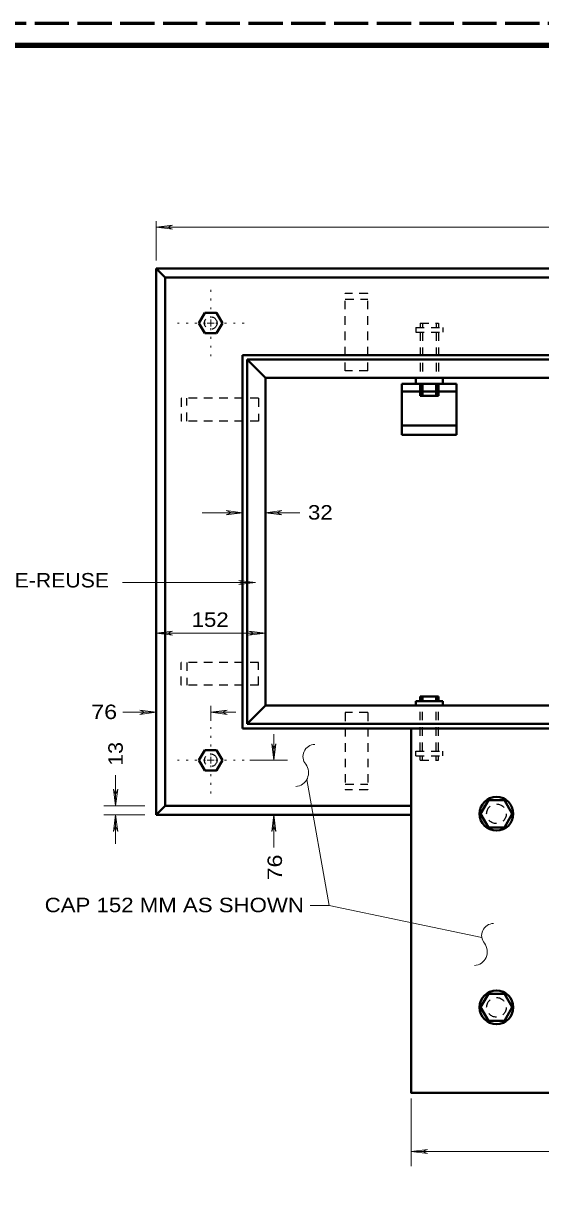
# Model space of a CAD drawing. Extents: x 312583 to 312853, y 144419 to 144586.
# Drawn here: x 312631.1 to 312658.3, y 144524.7 to 144586.2 of the extents above; entities that cross this region are included whole.
import ezdxf

# ---------------------------------------------------------------- set-up
doc = ezdxf.new("R2010")
doc.units = 0
doc.header["$LTSCALE"] = 0.3
for name, pattern in [('DOTTED', [1.5, 0.3, -1.2]), ('LONG_DASHED', [7.5, 6, -1.5]), ('SHORT_DASHED', [2.7, 1.5, -1.2])]:
    doc.linetypes.add(name, pattern=pattern)
doc.layers.add('1', color=7, linetype='Continuous', lineweight=40)
doc.layers.add('2', color=7, linetype='Continuous', lineweight=13)

msp = doc.modelspace()

# ---------------------------------------------------------------- linework, layer by layer
at = {"layer": '1', "linetype": 'LONG_DASHED', "lineweight": 60}
msp.add_line((312851.75, 144586.2246), (312583.526, 144586.2246), dxfattribs=at)
msp.add_line((312851.75, 144586.2246), (312583.526, 144586.2246), dxfattribs=at)
at = {"layer": '1'}
for p, q in [((312638.0888, 144573.3329), (312684.0888, 144573.3329)), ((312638.0888, 144573.3329), (312638.0888, 144544.5829)), ((312638.0888, 144573.3329), (312638.5641, 144572.8576)), ((312638.5641, 144572.8576), (312638.5641, 144545.0659)), ((312640.3351, 144570.4579), (312640.6495, 144570.9946)), ((312640.3351, 144570.4579), (312640.6495, 144569.9213)), ((312641.2705, 144569.9213), (312641.5848, 144570.4579)), ((312640.6495, 144569.9213), (312641.2705, 144569.9213)), ((312642.6351, 144568.7789), (312642.6351, 144549.1369)), ((312642.8805, 144568.5413), (312642.8805, 144549.3746)), ((312642.8805, 144568.5413), (312643.8388, 144567.5829)), ((312643.8388, 144567.5829), (312665.0141, 144567.5829)), ((312651.0225, 144567.2609), (312651.0225, 144564.5853)), ((312651.0225, 144567.2609), (312653.8975, 144567.2609)), ((312651.7431, 144567.2609), (312651.7431, 144567.5829)), ((312651.9808, 144566.6246), (312651.9808, 144567.2609)), ((312652.1035, 144566.6246), (312652.1035, 144567.2609)), ((312652.8165, 144566.6246), (312652.8165, 144567.2609)), ((312652.9391, 144566.6246), (312652.9391, 144567.2609)), ((312653.1768, 144567.2609), (312653.1768, 144567.5829)), ((312653.8975, 144567.2609), (312653.8975, 144564.5853)), ((312651.0225, 144566.8623), (312653.8975, 144566.8623)), ((312651.9808, 144566.6246), (312652.9391, 144566.6246)), ((312651.0225, 144565.0683), (312653.8975, 144565.0683)), ((312651.0225, 144564.5853), (312653.8975, 144564.5853)), ((312651.7431, 144550.5706), (312653.1768, 144550.5706)), ((312651.7431, 144550.5706), (312651.7431, 144550.3329)), ((312651.9808, 144550.8159), (312652.9391, 144550.8159)), ((312651.9808, 144550.8159), (312651.9808, 144550.5706)), ((312652.1035, 144550.8159), (312652.1035, 144550.5706)), ((312652.8165, 144550.8159), (312652.8165, 144550.5706)), ((312652.9391, 144550.8159), (312652.9391, 144550.5706)), ((312653.1768, 144550.5706), (312653.1768, 144550.3329)), ((312643.8388, 144550.3329), (312642.8805, 144549.3746)), ((312642.8805, 144549.3746), (312679.2971, 144549.3746)), ((312642.6351, 144549.1369), (312679.5348, 144549.1369)), ((312640.3351, 144547.4579), (312640.6495, 144547.9946)), ((312640.3351, 144547.4579), (312640.6495, 144546.9213)), ((312640.6495, 144547.9946), (312641.2705, 144547.9946)), ((312641.2705, 144547.9946), (312641.5848, 144547.4579)), ((312638.0888, 144544.5829), (312638.5641, 144545.0659)), ((312638.5641, 144545.0659), (312651.5055, 144545.0659)), ((312655.1625, 144544.6443), (312655.5765, 144545.3649)), ((312655.5765, 144545.3649), (312656.4121, 144545.3649)), ((312656.4121, 144545.3649), (312656.8261, 144544.6443)), ((312638.0888, 144544.5829), (312651.5055, 144544.5829)), ((312655.1625, 144544.6443), (312655.5765, 144543.9236)), ((312655.1625, 144534.4629), (312655.5765, 144535.1759)), ((312655.5765, 144535.1759), (312656.4121, 144535.1759)), ((312656.4121, 144535.1759), (312656.8261, 144534.4629)), ((312655.1625, 144534.4629), (312655.5765, 144533.7423))]:
    msp.add_line(p, q, dxfattribs=at)
at = {"layer": '1', "linetype": 'SHORT_DASHED', "lineweight": 25}
for p, q in [((312649.2285, 144572.0143), (312648.0325, 144572.0143)), ((312648.0325, 144567.9433), (312648.0325, 144572.0143)), ((312648.0325, 144571.7153), (312649.2285, 144571.7153)), ((312649.2285, 144567.9433), (312649.2285, 144572.0143)), ((312651.7431, 144570.2203), (312653.1768, 144570.2203)), ((312651.7431, 144570.2203), (312651.7431, 144569.9826)), ((312651.9808, 144570.4579), (312652.9391, 144570.4579)), ((312651.9808, 144570.4579), (312651.9808, 144570.2203)), ((312652.1035, 144570.4579), (312652.1035, 144570.2203)), ((312652.8165, 144570.4579), (312652.8165, 144570.2203)), ((312652.9391, 144570.4579), (312652.9391, 144570.2203)), ((312653.1768, 144570.2203), (312653.1768, 144569.9826)), ((312651.7431, 144569.9826), (312653.1768, 144569.9826)), ((312651.9808, 144569.9826), (312651.9808, 144567.5829)), ((312652.1035, 144569.9826), (312652.1035, 144567.5829)), ((312652.8165, 144569.9826), (312652.8165, 144567.5829)), ((312652.9391, 144569.9826), (312652.9391, 144567.5829)), ((312649.2285, 144567.9433), (312648.0325, 144567.9433)), ((312639.4075, 144566.5019), (312639.4075, 144565.3059)), ((312643.4785, 144566.5019), (312639.4075, 144566.5019)), ((312639.7065, 144565.3059), (312639.7065, 144566.5019)), ((312643.4785, 144566.5019), (312643.4785, 144565.3059)), ((312643.4785, 144565.3059), (312639.4075, 144565.3059)), ((312639.4075, 144551.4139), (312639.4075, 144552.6099)), ((312643.4785, 144552.6099), (312639.4075, 144552.6099)), ((312639.7065, 144552.6099), (312639.7065, 144551.4139)), ((312643.4785, 144551.4139), (312643.4785, 144552.6099)), ((312643.4785, 144551.4139), (312639.4075, 144551.4139)), ((312649.2285, 144549.9726), (312648.0325, 144549.9726)), ((312648.0325, 144549.9726), (312648.0325, 144545.9093)), ((312649.2285, 144549.9726), (312649.2285, 144545.9093)), ((312651.9808, 144547.9409), (312651.9808, 144550.3329)), ((312652.1035, 144547.9409), (312652.1035, 144550.3329)), ((312652.8165, 144547.9409), (312652.8165, 144550.3329)), ((312652.9391, 144547.9409), (312652.9391, 144550.3329)), ((312651.7431, 144547.9409), (312653.1768, 144547.9409)), ((312651.7431, 144547.6956), (312651.7431, 144547.9409)), ((312651.7431, 144547.6956), (312653.1768, 144547.6956)), ((312651.9808, 144547.4579), (312651.9808, 144547.6956)), ((312651.9808, 144547.4579), (312652.9391, 144547.4579)), ((312652.1035, 144547.4579), (312652.1035, 144547.6956)), ((312652.8165, 144547.4579), (312652.8165, 144547.6956)), ((312652.9391, 144547.4579), (312652.9391, 144547.6956)), ((312653.1768, 144547.6956), (312653.1768, 144547.9409)), ((312648.0325, 144546.2006), (312649.2285, 144546.2006)), ((312649.2285, 144545.9093), (312648.0325, 144545.9093))]:
    msp.add_line(p, q, dxfattribs=at)
at = {"layer": '1', "lineweight": 158}
msp.add_lwpolyline([(312616.5, 144423.1446), (312616.5, 144585.0846), (312849, 144585.0846)], dxfattribs=at)
at = {"layer": '1'}
for points in [[(312638.5641, 144572.8576), (312683.6058, 144572.8576), (312683.6058, 144545.0659)], [(312640.6495, 144570.9946), (312641.2705, 144570.9946), (312641.5848, 144570.4579)], [(312642.6351, 144568.7789), (312679.5348, 144568.7789), (312679.5348, 144549.1369)], [(312642.8805, 144568.5413), (312679.2971, 144568.5413), (312679.2971, 144549.3746)], [(312643.8388, 144567.5829), (312643.8388, 144550.3329), (312678.3388, 144550.3329)], [(312651.5055, 144549.1369), (312651.5055, 144529.9703), (312670.6721, 144529.9703)], [(312640.6495, 144546.9213), (312641.2705, 144546.9213), (312641.5848, 144547.4579)], [(312655.5765, 144543.9236), (312656.4121, 144543.9236), (312656.8261, 144544.6443)], [(312655.5765, 144533.7423), (312656.4121, 144533.7423), (312656.8261, 144534.4629)]]:
    msp.add_lwpolyline(points, dxfattribs=at)
at = {"layer": '1', "linetype": 'SHORT_DASHED', "lineweight": 25}
for centre, radius in [((312640.96, 144570.4579), 0.3301), ((312640.96, 144547.4579), 0.3301), ((312655.9933, 144544.6433), 0.5157), ((312655.9933, 144534.4601), 0.5157)]:
    msp.add_circle(centre, radius, dxfattribs=at)
at = {"layer": '1'}
for centre in [(312655.9933, 144544.6433), (312655.9933, 144534.4601)]:
    msp.add_circle(centre, 0.8865, dxfattribs=at)
at = {"layer": '2'}
for p, q in [((312638.0888, 144573.7546), (312638.0888, 144575.8169)), ((312638.0888, 144575.5103), (312638.9551, 144575.6176)), ((312638.0888, 144575.5103), (312684.0888, 144575.5103)), ((312638.0888, 144575.5103), (312638.9551, 144575.4029)), ((312638.9551, 144575.6176), (312638.6791, 144575.5103)), ((312638.9551, 144575.4029), (312638.6791, 144575.5103)), ((312640.9638, 144570.4579), (312640.7798, 144570.4579)), ((312640.9638, 144570.4579), (312640.9638, 144570.6419)), ((312640.9638, 144570.4579), (312641.1401, 144570.4579)), ((312640.9638, 144570.4579), (312640.9638, 144570.2816)), ((312640.5115, 144560.4836), (312642.6351, 144560.4836)), ((312641.7688, 144560.5909), (312642.0448, 144560.4836)), ((312642.6351, 144560.4836), (312641.7688, 144560.5909)), ((312641.7688, 144560.3763), (312642.0448, 144560.4836)), ((312642.6351, 144560.4836), (312641.7688, 144560.3763)), ((312643.8388, 144560.4836), (312644.7051, 144560.5909)), ((312643.8388, 144560.4836), (312645.6481, 144560.4836)), ((312643.8388, 144560.4836), (312644.7051, 144560.3763)), ((312644.7051, 144560.5909), (312644.4291, 144560.4836)), ((312644.7051, 144560.3763), (312644.4291, 144560.4836)), ((312636.3101, 144556.8113), (312643.3098, 144556.8113)), ((312642.4435, 144556.9186), (312642.7195, 144556.8113)), ((312643.3098, 144556.8113), (312642.4435, 144556.9186)), ((312642.4435, 144556.7039), (312642.7195, 144556.8113)), ((312643.3098, 144556.8113), (312642.4435, 144556.7039)), ((312638.0888, 144554.1509), (312638.9551, 144554.2583)), ((312638.9551, 144554.2583), (312638.6791, 144554.1509)), ((312642.9725, 144554.2583), (312643.2485, 144554.1509)), ((312643.8388, 144554.1509), (312642.9725, 144554.2583)), ((312638.0888, 144554.1509), (312643.8388, 144554.1509)), ((312638.0888, 144554.1509), (312638.9551, 144554.0436)), ((312638.9551, 144554.0436), (312638.6791, 144554.1509)), ((312642.9725, 144554.0436), (312643.2485, 144554.1509)), ((312643.8388, 144554.1509), (312642.9725, 144554.0436)), ((312636.3408, 144549.9803), (312638.0888, 144549.9803)), ((312637.2225, 144550.0876), (312637.4985, 144549.9803)), ((312638.0888, 144549.9803), (312637.2225, 144550.0876)), ((312637.2225, 144549.8729), (312637.4985, 144549.9803)), ((312638.0888, 144549.9803), (312637.2225, 144549.8729)), ((312640.9638, 144549.5279), (312640.9638, 144550.3176)), ((312640.9638, 144549.9803), (312641.8301, 144550.0876)), ((312640.9638, 144549.9803), (312642.2748, 144549.9803)), ((312640.9638, 144549.9803), (312641.8301, 144549.8729)), ((312641.8301, 144550.0876), (312641.5541, 144549.9803)), ((312641.8301, 144549.8729), (312641.5541, 144549.9803)), ((312644.2835, 144547.4579), (312644.2835, 144548.8379)), ((312644.1761, 144548.3243), (312644.2835, 144548.0483)), ((312644.2835, 144547.4579), (312644.1761, 144548.3243)), ((312644.3908, 144548.3243), (312644.2835, 144548.0483)), ((312644.2835, 144547.4579), (312644.3908, 144548.3243)), ((312640.9638, 144547.4579), (312640.7798, 144547.4579)), ((312640.9638, 144547.4579), (312640.9638, 144547.6419)), ((312640.9638, 144547.4579), (312641.1401, 144547.4579)), ((312640.9638, 144547.4579), (312640.9638, 144547.2816)), ((312643.0261, 144547.4579), (312644.9965, 144547.4579)), ((312635.9575, 144545.0659), (312635.9575, 144546.6683)), ((312635.8501, 144545.9323), (312635.9575, 144545.6563)), ((312635.9575, 144545.0659), (312635.8501, 144545.9323)), ((312636.0648, 144545.9323), (312635.9575, 144545.6563)), ((312635.9575, 144545.0659), (312636.0648, 144545.9323)), ((312637.4985, 144545.0659), (312635.3365, 144545.0659)), ((312637.4985, 144544.5829), (312635.3365, 144544.5829)), ((312635.9575, 144544.5829), (312635.8501, 144543.7166)), ((312635.9575, 144543.0684), (312635.9575, 144544.5829)), ((312635.9575, 144544.5829), (312636.0648, 144543.7166)), ((312644.2835, 144544.5829), (312644.1761, 144543.7166)), ((312644.2835, 144542.8656), (312644.2835, 144544.5829)), ((312644.2835, 144544.5829), (312644.3908, 144543.7166)), ((312635.8501, 144543.7166), (312635.9575, 144543.9926)), ((312636.0648, 144543.7166), (312635.9575, 144543.9926)), ((312644.1761, 144543.7166), (312644.2835, 144543.9926)), ((312644.3908, 144543.7166), (312644.2835, 144543.9926)), ((312647.1968, 144539.8219), (312655.2238, 144538.1429)), ((312651.5055, 144529.6636), (312651.5055, 144526.1063)), ((312651.5055, 144526.8729), (312652.3718, 144526.9803)), ((312651.5055, 144526.8729), (312670.6721, 144526.8729)), ((312651.5055, 144526.8729), (312652.3718, 144526.7656)), ((312652.3718, 144526.9803), (312652.0958, 144526.8729)), ((312652.3718, 144526.7656), (312652.0958, 144526.8729))]:
    msp.add_line(p, q, dxfattribs=at)
at = {"layer": '2', "linetype": 'DOTTED'}
for p, q in [((312640.9638, 144570.7263), (312640.9638, 144572.5279)), ((312640.6878, 144570.4579), (312638.8938, 144570.4579)), ((312640.9638, 144570.1896), (312640.9638, 144568.3879)), ((312641.2321, 144570.4579), (312643.0261, 144570.4579)), ((312640.9638, 144547.7263), (312640.9638, 144549.5279)), ((312640.6878, 144547.4579), (312638.8938, 144547.4579)), ((312641.2321, 144547.4579), (312643.0261, 144547.4579)), ((312640.9638, 144547.1896), (312640.9638, 144545.3879))]:
    msp.add_line(p, q, dxfattribs=at)
at = {"layer": '2'}
msp.add_lwpolyline([(312646.1848, 144539.8219), (312647.1968, 144539.8219), (312646.0085, 144546.4383)], dxfattribs=at)
for centre, radius, start, end in [((312646.4464, 144547.6568), 0.6341, 91.07374, 220.22244), ((312645.3732, 144546.8076), 0.735, 274.68748, 36.73556), ((312655.8477, 144538.2373), 0.6341, 91.07374, 220.22244), ((312654.7745, 144537.3882), 0.735, 274.68748, 36.73556)]:
    msp.add_arc(centre, radius, start, end, dxfattribs=at)

# ---------------------------------------------------------------- texts
for s, width, p in [('32 ', 1.15, (312646.0775, 144560.1216)), ('INSTALL NEW FRAME-REUSE', 1.1, (312619.7083, 144556.5496)), ('152 ', 1.15, (312639.9549, 144554.4769)), ('76 ', 1.2, (312634.6768, 144549.6259)), ('CAP 152 MM AS SHOWN', 1.15, (312632.2246, 144539.4648))]:
    msp.add_text(s, height=0.76, dxfattribs=dict(at, width=width)).set_placement(p)
for s, width, p in [('13 ', 1.1, (312636.3319, 144547.1755)), ('76 ', 1.2, (312644.7098, 144541.1418))]:
    msp.add_text(s, height=0.76, rotation=90, dxfattribs=dict(at, width=width)).set_placement(p)

doc.saveas('drawing.dxf')
